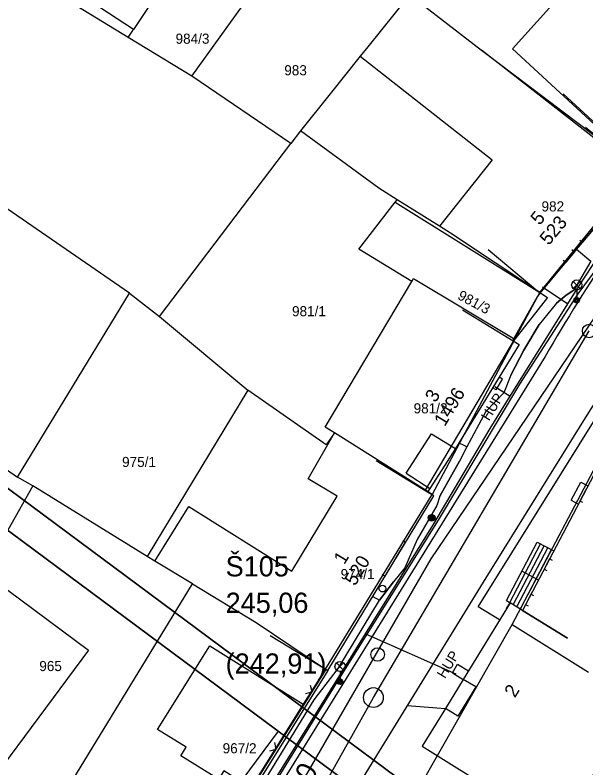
# Model space of a CAD drawing. Extents: x -601580 to 4, y -1204314 to 4.
# Drawn here: x -600239.8 to -600197.5, y -1203687.9 to -1203632.1 of the extents above; entities that cross this region are included whole.
import ezdxf

# ---------------------------------------------------------------- set-up
doc = ezdxf.new("R2010")
doc.units = 0
for name, color, linetype in [('00-INNOGY-NTL', 7, 'Continuous'), ('00-KN-HRANICE PARCEL', 7, 'Continuous'), ('00-KN-PARC. CISLA', 7, 'Continuous'), ('00-KN-VNITRNI KRESBA', 7, 'Continuous'), ('00-POLOHOPIS', 7, 'Continuous'), ('00-RAZÍTKO', 7, 'Continuous'), ('00-SITE KOM. KABEL', 7, 'Continuous'), ('00-VAK-KANAL-POTRUBI', 7, 'Continuous'), ('00-VAK-VODA-RAD IGIS', 7, 'Continuous'), ('Vrstva 25', 7, 'Continuous'), ('Vrstva 27', 7, 'Continuous'), ('Vrstva 28', 7, 'Continuous'), ('Vrstva 33', 7, 'Continuous'), ('Vrstva 6', 7, 'Continuous')]:
    doc.layers.add(name, color=color, linetype=linetype)

# ---------------------------------------------------------------- blocks, each defined once
blk = doc.blocks.new('6.01A_1048')
at = {"layer": 'Vrstva 25'}
for radius in [0.25, 0.2, 0.15, 0.1, 0.05]:
    blk.add_circle((0, 0), radius, dxfattribs=at)
blk = doc.blocks.new('6.14A_204')
at = {"layer": 'Vrstva 28'}
blk.add_circle((0, 0), 0.25, dxfattribs=at)
blk = doc.blocks.new('VCHOD_1514')
at = {"layer": 'Vrstva 6'}
blk.add_line((0, 0.25), (0, 0), dxfattribs=at)
blk = doc.blocks.new('VCHOD_1516')
at = {"layer": 'Vrstva 6'}
blk.add_line((0, 0.25), (0, 0), dxfattribs=at)
blk = doc.blocks.new('6.560_980')
at = {"layer": 'Vrstva 33'}
for p, q in [((-0.265, 0.86), (0.265, 1.39)), ((-0.265, 1.39), (0.265, 0.86)), ((0, 0.75), (0, 0))]:
    blk.add_line(p, q, dxfattribs=at)
for centre, radius in [((0, 1.125), 0.375), ((0, 0), 0.2), ((0, 0), 0.145), ((0, 0), 0.0876)]:
    blk.add_circle(centre, radius, dxfattribs=at)
blk = doc.blocks.new('6.20_334')
at = {"layer": 'Vrstva 27'}
blk.add_circle((0, 0), 0.5, dxfattribs=at)
blk = doc.blocks.new('6.560_982')
at = {"layer": 'Vrstva 33'}
for p, q in [((-0.265, 0.86), (0.265, 1.39)), ((-0.265, 1.39), (0.265, 0.86)), ((0, 0.75), (0, 0))]:
    blk.add_line(p, q, dxfattribs=at)
for centre, radius in [((0, 1.125), 0.375), ((0, 0), 0.2), ((0, 0), 0.145), ((0, 0), 0.0876)]:
    blk.add_circle(centre, radius, dxfattribs=at)
blk = doc.blocks.new('VCHOD_1524')
at = {"layer": 'Vrstva 6'}
blk.add_line((0, 0.25), (0, 0), dxfattribs=at)
blk = doc.blocks.new('VCHOD_1526')
at = {"layer": 'Vrstva 6'}
blk.add_line((0, 0.25), (0, 0), dxfattribs=at)
blk = doc.blocks.new('VCHOD_1528')
at = {"layer": 'Vrstva 6'}
blk.add_line((0, 0.25), (0, 0), dxfattribs=at)
blk = doc.blocks.new('6.20_336')
at = {"layer": 'Vrstva 27'}
blk.add_circle((0, 0), 0.5, dxfattribs=at)
blk = doc.blocks.new('VCHOD_2392')
at = {"layer": 'Vrstva 6'}
blk.add_line((0, 0.25), (0, 0), dxfattribs=at)
blk = doc.blocks.new('VCHOD_2394')
at = {"layer": 'Vrstva 6'}
blk.add_line((0, 0.25), (0, 0), dxfattribs=at)
blk = doc.blocks.new('VCHOD_2396')
at = {"layer": 'Vrstva 6'}
blk.add_line((0, 0.25), (0, 0), dxfattribs=at)
blk = doc.blocks.new('VCHOD_2398')
at = {"layer": 'Vrstva 6'}
blk.add_line((0, 0.25), (0, 0), dxfattribs=at)
blk = doc.blocks.new('VCHOD_2400')
at = {"layer": 'Vrstva 6'}
blk.add_line((0, 0.25), (0, 0), dxfattribs=at)

msp = doc.modelspace()

# ---------------------------------------------------------------- linework, layer by layer
for points in [[(-600250.091, -1203790.762), (-600248.083, -1203792.252), (-600185.471, -1203707.9), (-600304.712, -1203619.391), (-600367.324, -1203703.744), (-600365.317, -1203705.234)], [(-600248.601, -1203788.755), (-600188.969, -1203708.417), (-600304.195, -1203622.889), (-600363.827, -1203703.226)]]:
    msp.add_lwpolyline(points)
at = {"layer": '00-INNOGY-NTL'}
for p, q in [((-600200.76, -1203652.23), (-600198.88, -1203653.48)), ((-600204.29, -1203659.62), (-600203.15, -1203660.33)), ((-600213.87, -1203677.91), (-600207.19, -1203680.88))]:
    msp.add_line(p, q, dxfattribs=at)
msp.add_lwpolyline([(-600240.2, -1203720.25), (-600231.48, -1203706.17), (-600223.49, -1203693.36), (-600215.31, -1203680.24), (-600213.87, -1203677.91), (-600208.88, -1203669.89), (-600204.63, -1203662.71), (-600203.15, -1203660.33), (-600198.88, -1203653.48), (-600198.19, -1203652.37), (-600196.44, -1203649.71), (-600194.5, -1203646.75), (-600192.66, -1203646.1), (-600191.34, -1203644.27), (-600190.94, -1203641.91), (-600187.06, -1203637.49), (-600183.73, -1203633.69), (-600183.52, -1203633.46), (-600182, -1203631.75)], dxfattribs=at)
at = {"layer": '00-KN-HRANICE PARCEL'}
for p, q in [((-600226.74, -1203636.63), (-600218.89, -1203625.72)), ((-600227.78, -1203628.25), (-600231.06, -1203633.17)), ((-600231.37, -1203652.7), (-600262.78, -1203631.03)), ((-600231.45, -1203633.76), (-600231.06, -1203633.17)), ((-600226.74, -1203636.63), (-600231.45, -1203633.76)), ((-600219.42, -1203641.63), (-600226.74, -1203636.63)), ((-600218.69, -1203640.67), (-600219.42, -1203641.63)), ((-600212.89, -1203644.93), (-600218.69, -1203640.67)), ((-600229.14, -1203654.43), (-600219.42, -1203641.63)), ((-600193.38, -1203643.69), (-600200.97, -1203652.66)), ((-600211.53, -1203645.78), (-600212.89, -1203644.93)), ((-600208.39, -1203647.75), (-600211.53, -1203645.78)), ((-600239.65, -1203666.33), (-600231.37, -1203652.7)), ((-600231.37, -1203652.7), (-600229.14, -1203654.43)), ((-600202.8, -1203656.1), (-600200.97, -1203652.66)), ((-600229.14, -1203654.43), (-600222.59, -1203659.89)), ((-600202.8, -1203656.1), (-600208.94, -1203667.6)), ((-600222.59, -1203659.89), (-600230.05, -1203672.19)), ((-600238.52, -1203666.97), (-600239.65, -1203666.33)), ((-600238.52, -1203666.97), (-600241.56, -1203672.31)), ((-600230.05, -1203672.19), (-600238.52, -1203666.97)), ((-600216.85, -1203680.53), (-600208.94, -1203667.6)), ((-600236.19, -1203689.73), (-600226.69, -1203674.22)), ((-600216.85, -1203680.53), (-600218.49, -1203683.14)), ((-600218.49, -1203683.14), (-600222.37, -1203689.32))]:
    msp.add_line(p, q, dxfattribs=at)
for points in [[(-600231.45, -1203633.76), (-600238.61, -1203629.39), (-600249.22, -1203620.27)], [(-600231.06, -1203633.17), (-600237.91, -1203628.69), (-600234.37, -1203623.57), (-600233.71, -1203624.03), (-600233.95, -1203624.37), (-600227.78, -1203628.25)], [(-600186.89, -1203632.05), (-600195.64, -1203641.37), (-600202.99, -1203634.6), (-600194.54, -1203625.23)], [(-600210.66, -1203630.66), (-600213.71, -1203634.46), (-600214.26, -1203635.15), (-600216.5, -1203637.94), (-600218.69, -1203640.67)], [(-600210.59, -1203630.58), (-600205.27, -1203634.72), (-600193.38, -1203643.69)], [(-600210.44, -1203651.83), (-600214.37, -1203649.45), (-600211.67, -1203645.96), (-600211.53, -1203645.78)], [(-600200.97, -1203652.66), (-600207.59, -1203648.25), (-600208.39, -1203647.75)], [(-600210.44, -1203651.83), (-600210.31, -1203651.61), (-600202.8, -1203656.1)], [(-600216.17, -1203663.05), (-600216.86, -1203662.62), (-600210.44, -1203651.83)], [(-600200.97, -1203652.66), (-600200.38, -1203653.02), (-600202.8, -1203656.1)], [(-600259.09, -1203653.54), (-600244.5, -1203662.97), (-600239.65, -1203666.33)], [(-600216.17, -1203663.05), (-600216.79, -1203663.94), (-600222.59, -1203659.89)], [(-600215.29, -1203698.75), (-600203, -1203677.22), (-600195.14, -1203662.33), (-600194.85, -1203661.79)], [(-600208.94, -1203667.6), (-600209.44, -1203667.29), (-600216.17, -1203663.05)], [(-600226.69, -1203674.22), (-600229.48, -1203672.54), (-600230.05, -1203672.19)], [(-600226.69, -1203674.22), (-600221.97, -1203677.08), (-600216.85, -1203680.53)], [(-600222.37, -1203689.32), (-600224.37, -1203688.06), (-600224.77, -1203688.69), (-600227.56, -1203686.96), (-600227.17, -1203686.32), (-600229.29, -1203685.01), (-600225.42, -1203678.8), (-600218.49, -1203683.14)]]:
    msp.add_lwpolyline(points, dxfattribs=at)
at = {"layer": '00-KN-VNITRNI KRESBA'}
for p, q in [((-600211.67, -1203645.96), (-600200.97, -1203652.66)), ((-600209.44, -1203667.29), (-600202.8, -1203656.1)), ((-600203, -1203677.22), (-600197.36, -1203680.75))]:
    msp.add_line(p, q, dxfattribs=at)
for points in [[(-600200.97, -1203652.66), (-600193.71, -1203643.73), (-600205.27, -1203634.72)], [(-600214.26, -1203635.15), (-600204.49, -1203642.83), (-600208.39, -1203647.75)], [(-600229.48, -1203672.54), (-600226.96, -1203668.5), (-600219.33, -1203673.28), (-600215.98, -1203667.73), (-600218.12, -1203666.45), (-600216.17, -1203663.05)]]:
    msp.add_lwpolyline(points, dxfattribs=at)
at = {"layer": '00-POLOHOPIS'}
for p, q in [((-600195.806, -1203646.529), (-600197.811, -1203648.932)), ((-600198.401, -1203649.639), (-600199.042, -1203650.406)), ((-600190.213, -1203650.177), (-600197.606, -1203661.919)), ((-600200.952, -1203652.695), (-600201.144, -1203652.956)), ((-600202.968, -1203656.207), (-600201.144, -1203652.956)), ((-600200.565, -1203657.379), (-600225.374, -1203697.491)), ((-600203.723, -1203659.069), (-600203.979, -1203658.912)), ((-600204.203, -1203659.854), (-600203.723, -1203659.069)), ((-600204.203, -1203659.854), (-600204.459, -1203659.697)), ((-600197.606, -1203661.919), (-600204.959, -1203673.768)), ((-600210.863, -1203666.038), (-600208.994, -1203663.123)), ((-600208.994, -1203663.123), (-600207.22, -1203664.209)), ((-600210.863, -1203666.038), (-600209.112, -1203667.16)), ((-600198.633, -1203668.033), (-600197.925, -1203666.688)), ((-600197.925, -1203666.688), (-600197.394, -1203666.967)), ((-600197.543, -1203667.25), (-600197.985, -1203668.091)), ((-600198.633, -1203668.033), (-600198.102, -1203668.312)), ((-600212.423, -1203673.643), (-600210.903, -1203671.138)), ((-600203.438, -1203675.458), (-600201.165, -1203671.131)), ((-600201.165, -1203671.131), (-600199.926, -1203671.782)), ((-600203.172, -1203675.597), (-600200.899, -1203671.27)), ((-600202.906, -1203675.737), (-600200.633, -1203671.41)), ((-600202.641, -1203675.876), (-600200.368, -1203671.549)), ((-600202.375, -1203676.016), (-600200.102, -1203671.689)), ((-600200.237, -1203672.375), (-600200.642, -1203673.145)), ((-600201.063, -1203673.944), (-600202.301, -1203673.294)), ((-600204.959, -1203673.768), (-600215.356, -1203690.63)), ((-600201.615, -1203674.995), (-600202.02, -1203675.765)), ((-600203.438, -1203675.458), (-600203.164, -1203675.626)), ((-600203.428, -1203676.057), (-600203.164, -1203675.626)), ((-600227.131, -1203697.053), (-600216.792, -1203680.554)), ((-600216.664, -1203680.632), (-600227.004, -1203697.133)), ((-600207.44, -1203680.797), (-600207.053, -1203680.165)), ((-600207.053, -1203680.165), (-600206.243, -1203680.661)), ((-600207.44, -1203680.797), (-600206.63, -1203681.293)), ((-600205.709, -1203681.856), (-600206.63, -1203681.293)), ((-600205.709, -1203681.856), (-600207.038, -1203684.02)), ((-600210.794, -1203683.231), (-600207.958, -1203683.455)), ((-600207.038, -1203684.02), (-600207.958, -1203683.455))]:
    msp.add_line(p, q, dxfattribs=at)
for points in [[(-600190.537, -1203628.498), (-600186.96, -1203631.992), (-600195.561, -1203641.332), (-600199.239, -1203637.945)], [(-600197.58, -1203640.398), (-600193.467, -1203643.727), (-600200.952, -1203652.695), (-600204.791, -1203649.491)], [(-600206.698, -1203653.924), (-600202.499, -1203656.494), (-600207.22, -1203664.209), (-600209.285, -1203667.43), (-600213.098, -1203665.116)], [(-600187.946, -1203663.685), (-600194.992, -1203662.397), (-600202.243, -1203676.19), (-600198.898, -1203678.235)], [(-600220.939, -1203678.038), (-600216.664, -1203680.632), (-600208.823, -1203667.71), (-600209.285, -1203667.43), (-600213.098, -1203665.116)], [(-600198.898, -1203678.235), (-600202.243, -1203676.19), (-600203.164, -1203675.626), (-600206.63, -1203681.293), (-600207.958, -1203683.455), (-600209.671, -1203686.249), (-600204.025, -1203689.768), (-600203.337, -1203688.665), (-600198.913, -1203691.433), (-600196.261, -1203687.194)], [(-600227.131, -1203697.053), (-600216.792, -1203680.554)], [(-600218.321, -1203682.335), (-600217.838, -1203682.224), (-600217.949, -1203681.742)], [(-600220.976, -1203686.572), (-600220.493, -1203686.461), (-600220.604, -1203685.978)]]:
    msp.add_lwpolyline(points, dxfattribs=at)
msp.add_arc((-600084.503, -1203724.484), 134.065, 141.97654, 149.96429, dxfattribs=at)
at = {"layer": '00-RAZÍTKO'}
for points in [[(-600492.548, -1203872.448), (-600304.712, -1203619.391), (-600185.471, -1203707.9), (-600373.307, -1203960.957)], [(-600489.051, -1203871.931), (-600304.195, -1203622.889), (-600188.969, -1203708.417), (-600373.825, -1203957.46)], [(-600188.969, -1203708.417), (-600246.123, -1203785.417), (-600325.417, -1203726.559), (-600268.263, -1203649.56)], [(-600295.297, -1203700.056), (-600263.642, -1203657.411), (-600234.397, -1203679.119), (-600266.051, -1203721.765)], [(-600188.969, -1203708.417), (-600246.123, -1203785.417), (-600310.751, -1203737.445), (-600253.597, -1203660.446)]]:
    msp.add_lwpolyline(points, close=True, dxfattribs=at)
msp.add_lwpolyline([(-600276.866, -1203761.304), (-600220.331, -1203685.138)], dxfattribs=at)
at = {"layer": '00-SITE KOM. KABEL'}
for points in [[(-600238.73, -1203718.32), (-600229.65, -1203703.65), (-600215.97, -1203681.5), (-600208.47, -1203669.5), (-600202.43, -1203659.43), (-600198.13, -1203652.76), (-600191.9, -1203644.36), (-600182.08, -1203632.22), (-600175.22, -1203624.74), (-600171.57, -1203620.8), (-600170.9, -1203620.45), (-600170.66, -1203619.82), (-600162.89, -1203611.32), (-600154.76, -1203602.44), (-600154.39, -1203600.87), (-600148.06, -1203593.79)], [(-600198.24, -1203649.45), (-600197.18, -1203650.34)], [(-600197.18, -1203650.34), (-600198.45, -1203652.49), (-600199.01, -1203652.84), (-600199.72, -1203653.43), (-600201.02, -1203655.02), (-600202.14, -1203656.92), (-600203.12, -1203658.77), (-600203.63, -1203660.08), (-600204.97, -1203661.47), (-600206.37, -1203664.07)], [(-600203.94, -1203676.89), (-600205.52, -1203675.93), (-600196.87, -1203662.03), (-600194.51, -1203658.16), (-600192.07, -1203654.3), (-600190.85, -1203652.41), (-600189.98, -1203651.03), (-600189.72, -1203650.61)], [(-600199.72, -1203653.43), (-600199.01, -1203652.84), (-600198.45, -1203652.49)], [(-600203.12, -1203658.77), (-600202.14, -1203656.92), (-600201.02, -1203655.02)], [(-600204.97, -1203661.47), (-600203.63, -1203660.08)], [(-600206.96, -1203663.78), (-600206.598, -1203663.958)], [(-600206.598, -1203663.958), (-600206.37, -1203664.07)], [(-600206.37, -1203664.07), (-600206.91, -1203665.14), (-600208.37, -1203667.72), (-600208.58, -1203668.43), (-600210.06, -1203670.93), (-600210.96, -1203673.04), (-600211.8, -1203674.07), (-600212.84, -1203675.43)], [(-600208.37, -1203667.72), (-600206.91, -1203665.14)], [(-600212.84, -1203675.43), (-600211.8, -1203674.07)], [(-600242.68, -1203718.95), (-600241.74, -1203718.93), (-600240.13, -1203718.64), (-600238.61, -1203717.09), (-600232.73, -1203707.68), (-600230.04, -1203703.32), (-600226.57, -1203697.57), (-600224.69, -1203694.97), (-600222.94, -1203692.01), (-600222.45, -1203690.59), (-600217.67, -1203682.82), (-600215.89, -1203680.49), (-600212.84, -1203675.43)], [(-600213.33, -1203675.16), (-600212.84, -1203675.43)]]:
    msp.add_lwpolyline(points, dxfattribs=at)
at = {"layer": '00-VAK-KANAL-POTRUBI'}
for points in [[(-600213.29, -1203682.64), (-600197.304, -1203655.497)], [(-600225.375, -1203704.212), (-600213.29, -1203682.64)]]:
    msp.add_lwpolyline(points, dxfattribs=at)
msp.add_circle((-600213.29, -1203682.64), 0.735, dxfattribs=at)
at = {"layer": '00-VAK-VODA-RAD IGIS'}
msp.add_lwpolyline([(-600189.723, -1203643.886), (-600209.039, -1203672.378), (-600226.824, -1203703.137), (-600234.083, -1203715.623)], dxfattribs=at)

# ---------------------------------------------------------------- block references
at = {"layer": '00-POLOHOPIS'}
for name, p, xscale, yscale, rotation in [('VCHOD_1524', (-600197.811, -1203648.932), 1.00000287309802, 1.00000287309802, 50.15924333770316), ('VCHOD_1526', (-600198.401, -1203649.639), 1.00000069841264, 1.0000006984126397, 50.11360438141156), ('VCHOD_1528', (-600199.042, -1203650.406), 1.00000069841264, 1.0000006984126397, 50.11360438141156), ('VCHOD_2392', (-600197.985, -1203668.091), 0.9999984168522, 0.9999984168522, -117.72479062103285), ('VCHOD_1514', (-600210.903, -1203671.138), 1.00000099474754, 1.0000009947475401, 58.75113300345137), ('VCHOD_2394', (-600200.237, -1203672.375), 0.9999987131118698, 0.9999987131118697, -117.74316920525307), ('VCHOD_2396', (-600200.642, -1203673.145), 0.9999987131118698, 0.9999987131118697, -117.74316920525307), ('VCHOD_1516', (-600212.423, -1203673.643), 1.00000099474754, 1.0000009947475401, 58.75113300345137), ('VCHOD_2398', (-600201.615, -1203674.995), 0.9999987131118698, 0.9999987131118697, -117.74316920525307), ('VCHOD_2400', (-600202.02, -1203675.765), 0.9999987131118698, 0.9999987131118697, -117.74316920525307), ('6.20_336', (-600212.979, -1203679.454), 0.9999981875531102, 0.9999981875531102, 58.5191855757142)]:
    msp.add_blockref(name, p, dxfattribs=dict(at, xscale=xscale, yscale=yscale, rotation=rotation))
for name, p in [('6.560_982', (-600198.227, -1203653.22)), ('6.20_334', (-600197.304, -1203655.497)), ('6.560_980', (-600215.764, -1203681.47))]:
    msp.add_blockref(name, p, dxfattribs=at)
at = {"layer": '00-POLOHOPIS', "rotation": -90.00000000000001}
for name, p in [('6.01A_1048', (-600208.976, -1203669.331)), ('6.14A_204', (-600212.621, -1203674.57))]:
    msp.add_blockref(name, p, dxfattribs=at)

# ---------------------------------------------------------------- texts
at = {"layer": '00-KN-PARC. CISLA'}
for s, p in [('984/3', (-600227.947, -1203634.234)), ('983', (-600219.894, -1203636.57)), ('982', (-600200.834, -1203646.65)), ('981/1', (-600219.319, -1203654.41)), ('981/2', (-600210.31, -1203661.6)), ('975/1', (-600231.909, -1203665.57)), ('974/1', (-600215.719, -1203673.87)), ('965', (-600238.044, -1203680.68)), ('967/2', (-600224.46, -1203686.77))]:
    msp.add_text(s, height=0.75, dxfattribs=at).set_placement(p)
msp.add_text('981/3', height=0.75, rotation=332, dxfattribs=at).set_placement((-600207.112, -1203653.102))
at = {"layer": '00-POLOHOPIS'}
for s, height, rotation, p in [('5', 1, 50.1505, (-600200.978, -1203647.726)), ('523', 1, 50.1505, (-600200.301, -1203649.212)), ('3', 1, 58.5365, (-600208.685, -1203660.855)), ('1496', 1, 58.5365, (-600208.009, -1203662.625)), ('HUP', 0.75, 58.5557, (-600204.725, -1203662.207)), ('1', 1, 58.7509, (-600215.448, -1203672.846)), ('520', 1, 58.7509, (-600214.653, -1203674.426)), ('HUP', 0.75, 58.5191, (-600207.993, -1203681.282)), ('2', 1, 58.5496, (-600202.804, -1203682.705))]:
    msp.add_text(s, height=height, rotation=rotation, dxfattribs=at).set_placement(p)
at = {"layer": '00-VAK-KANAL-POTRUBI'}
for s, p in [('Š105', (-600224.239, -1203673.672)), ('245,06 ', (-600224.239, -1203676.372)), ('(242,91)', (-600224.239, -1203680.872))]:
    msp.add_text(s, height=1.5, dxfattribs=at).set_placement(p)
msp.add_text('B 500', height=1.5, rotation=60.74, dxfattribs=at).set_placement((-600219.905, -1203692.606))

doc.saveas('drawing.dxf')
